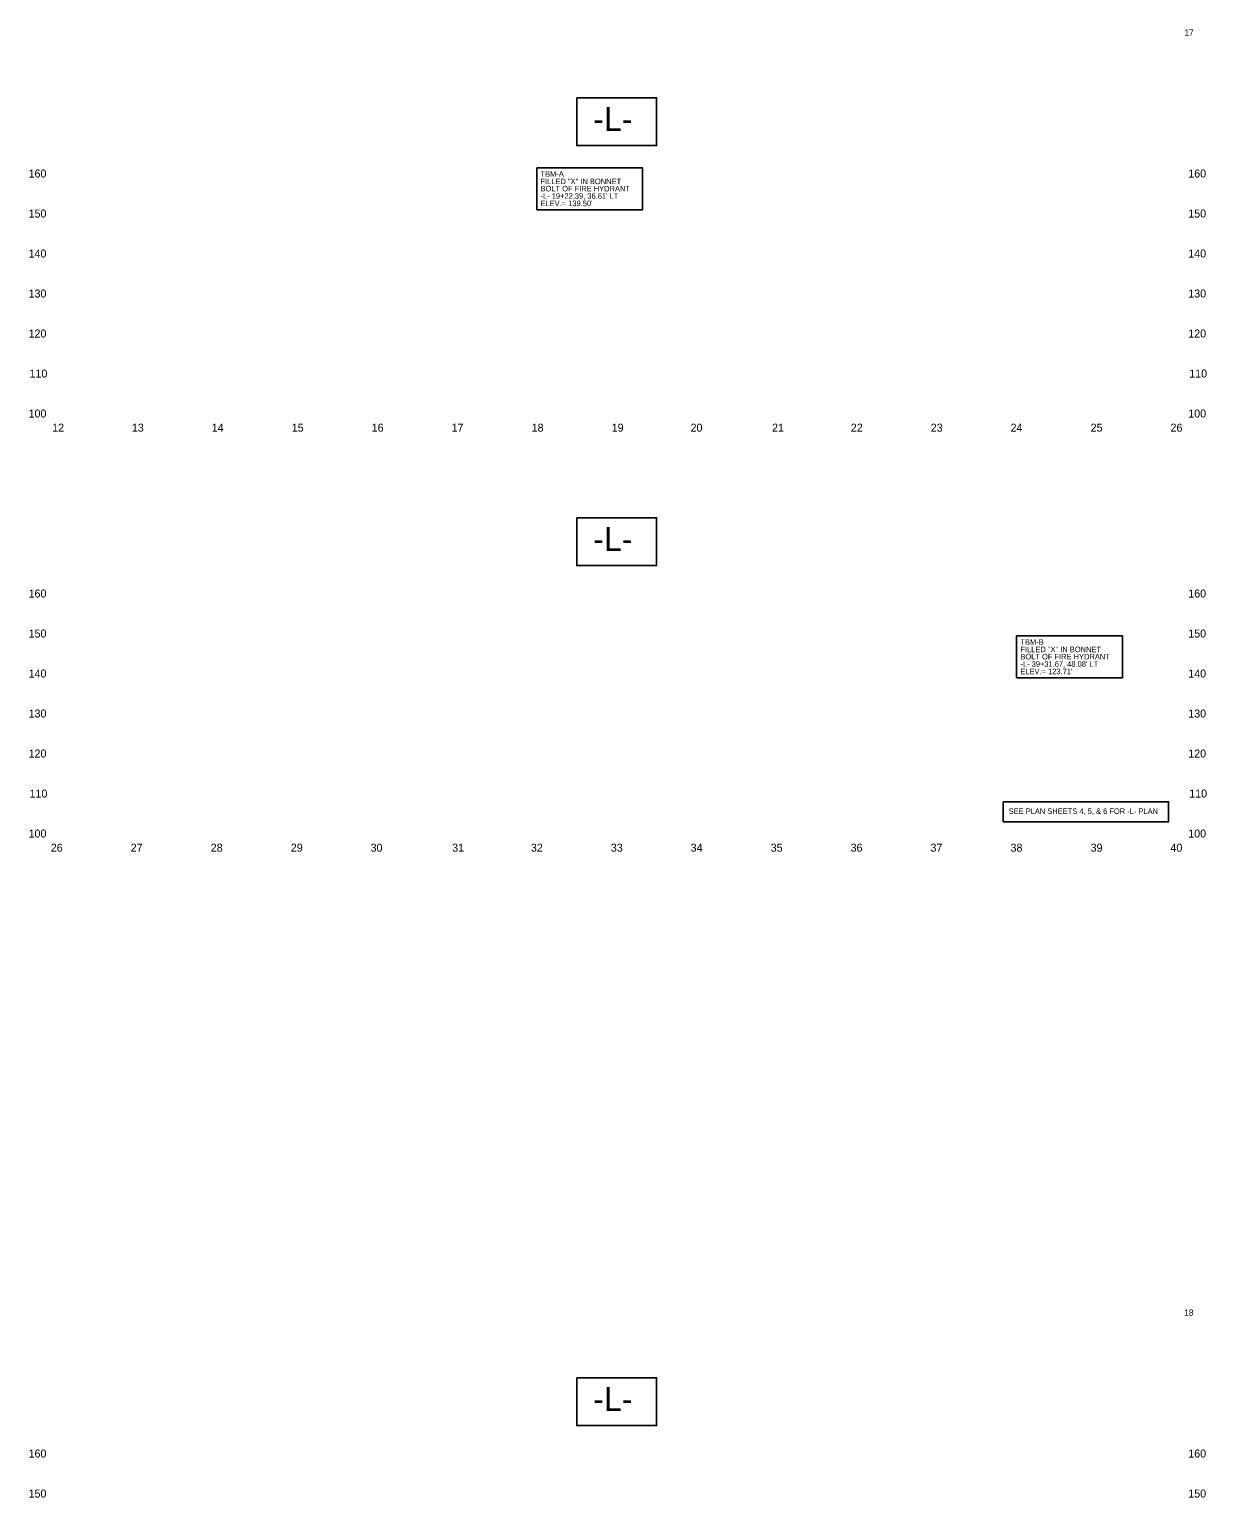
# Model space of a CAD drawing. Extents: x 2364289 to 2366249, y 588759 to 610062.
# Drawn here: x 2364469 to 2365941, y 608227 to 610062 of the extents above; entities that cross this region are included whole.
import ezdxf

# ---------------------------------------------------------------- set-up
doc = ezdxf.new("R2010")
doc.units = 0
for name, color, linetype in [('Exist Vertical Profile Horizontal Axis Label Major', 7, 'Continuous'), ('Exist Vertical Profile Vertical Axis Label', 7, 'Continuous'), ('Prop DSN Text', 7, 'Continuous'), ('Prop Grid Mask', 7, 'Continuous'), ('Sheet Data Field CELL', 7, 'Continuous')]:
    doc.layers.add(name, color=color, linetype=linetype)

msp = doc.modelspace()

# ---------------------------------------------------------------- linework, layer by layer
at = {"layer": 'Prop Grid Mask'}
for points in [[(2365153.5, 609976.5), (2365253.2, 609976.5), (2365253.2, 609916.6), (2365153.5, 609916.6)], [(2365103.3, 609888.7), (2365235.7, 609888.7), (2365235.7, 609836.5), (2365103.3, 609836.5)], [(2365153.5, 609451.5), (2365253.2, 609451.5), (2365253.2, 609391.6), (2365153.5, 609391.6)], [(2365703.3, 609303.7), (2365835.7, 609303.7), (2365835.7, 609251.5), (2365703.3, 609251.5)], [(2365686.7, 609096.5), (2365893.3, 609096.5), (2365893.3, 609071.5), (2365686.7, 609071.5)], [(2365153.5, 608376.5), (2365253.2, 608376.5), (2365253.2, 608316.6), (2365153.5, 608316.6)]]:
    msp.add_lwpolyline(points, close=True, dxfattribs=at)

# ---------------------------------------------------------------- texts
at = {"layer": 'Exist Vertical Profile Horizontal Axis Label Major'}
for s, p in [('12', (2364497.5, 609559)), ('13', (2364597.2, 609559)), ('14', (2364697, 609559)), ('15', (2364797.1, 609559)), ('16', (2364897, 609559)), ('17', (2364996.9, 609559)), ('18', (2365097, 609559)), ('19', (2365197.1, 609559)), ('20', (2365295.7, 609559)), ('21', (2365397.6, 609559)), ('22', (2365496.1, 609559)), ('23', (2365596, 609559)), ('24', (2365695.8, 609559)), ('25', (2365795.9, 609559)), ('26', (2365895.8, 609559)), ('26', (2364495.8, 609034)), ('27', (2364595.7, 609034)), ('28', (2364695.8, 609034)), ('29', (2364795.9, 609034)), ('30', (2364895.7, 609034)), ('31', (2364997.6, 609034)), ('32', (2365096.1, 609034)), ('33', (2365196, 609034)), ('34', (2365295.8, 609034)), ('35', (2365395.9, 609034)), ('36', (2365495.8, 609034)), ('37', (2365595.7, 609034)), ('38', (2365695.8, 609034)), ('39', (2365795.9, 609034)), ('40', (2365895.7, 609034))]:
    msp.add_text(s, height=10, dxfattribs=at).set_placement(p)
at = {"layer": 'Exist Vertical Profile Vertical Axis Label'}
for s, p in [('160', (2364468, 609876.7)), ('160', (2365918, 609876.7)), ('150', (2364468, 609826.7)), ('150', (2365918, 609826.7)), ('140', (2364468, 609776.7)), ('140', (2365918, 609776.7)), ('130', (2364468, 609726.7)), ('130', (2365918, 609726.7)), ('120', (2364468, 609676.7)), ('120', (2365918, 609676.7)), ('110', (2364469.2, 609626.7)), ('110', (2365919.2, 609626.7)), ('100', (2364468, 609576.7)), ('100', (2365918, 609576.7)), ('160', (2364468, 609351.7)), ('160', (2365918, 609351.7)), ('150', (2364468, 609301.7)), ('150', (2365918, 609301.7)), ('140', (2364468, 609251.7)), ('140', (2365918, 609251.7)), ('130', (2364468, 609201.7)), ('130', (2365918, 609201.7)), ('120', (2364468, 609151.7)), ('120', (2365918, 609151.7)), ('110', (2364469.2, 609101.7)), ('110', (2365919.2, 609101.7)), ('100', (2364468, 609051.7)), ('100', (2365918, 609051.7)), ('160', (2364468, 608276.7)), ('160', (2364468, 608276.7)), ('160', (2365918, 608276.7)), ('150', (2364468, 608226.7)), ('150', (2364468, 608226.7)), ('150', (2365918, 608226.7))]:
    msp.add_text(s, height=10, dxfattribs=at).set_placement(p)
at = {"layer": 'Prop DSN Text'}
for s, p in [('TBM-A', (2365108.1, 609877.6)), ('FILLED "X" IN BONNET ', (2365108.1, 609868.4)), ("-L- 19+22.39, 36.61' LT", (2365108.1, 609850.1)), ('BOLT OF FIRE HYDRANT', (2365108.1, 609859.3)), ("ELEV.= 139.50'", (2365108.1, 609840.9)), ('TBM-B', (2365708.1, 609292.6)), ('FILLED "X" IN BONNET ', (2365708.1, 609283.4)), ("-L- 39+31.67, 48.08' LT", (2365708.1, 609265.1)), ('BOLT OF FIRE HYDRANT', (2365708.1, 609274.3)), ("ELEV.= 123.71'", (2365708.1, 609255.9)), ('SEE PLAN SHEETS 4, 5, & 6 FOR -L- PLAN', (2365693.4, 609081.1))]:
    msp.add_text(s, height=7, dxfattribs=at).set_placement(p)
at = {"layer": 'Prop Grid Mask'}
for p in [(2365174, 609935), (2365174, 609410), (2365174, 608335)]:
    msp.add_text('-L-', height=30, dxfattribs=at).set_placement(p)
at = {"layer": 'Sheet Data Field CELL'}
for s, p in [('17', (2365913.2, 610054.1)), ('18', (2365912.9, 608454.1))]:
    msp.add_text(s, height=7.75, dxfattribs=at).set_placement(p)

doc.saveas('drawing.dxf')
